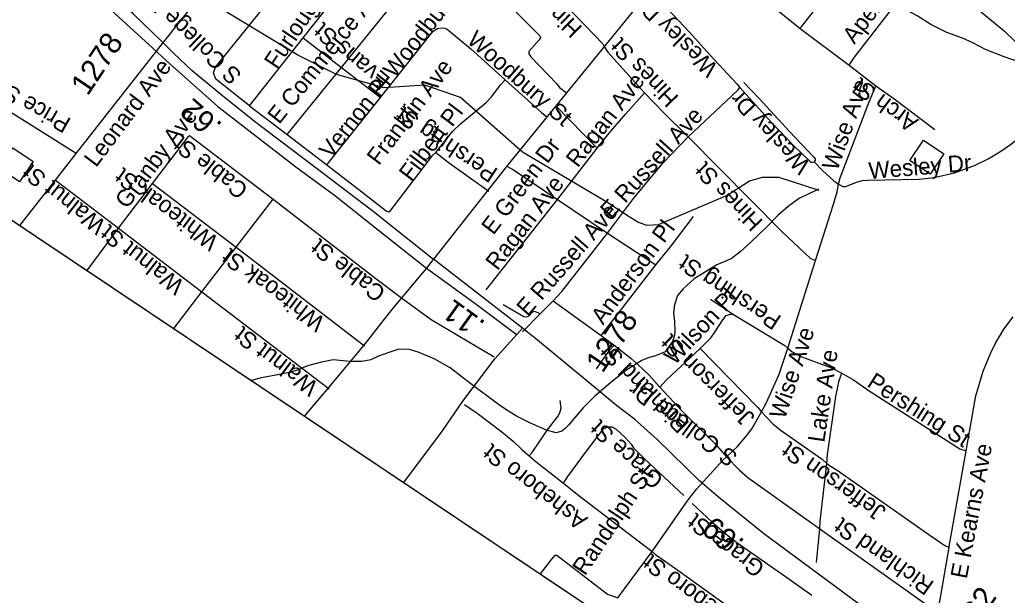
# Model space of a CAD drawing. Extents: x 1715610 to 1720914, y 798298 to 802505.
# Drawn here: x 1715709.6 to 1715831.7, y 799408.2 to 799479.3 of the extents above; entities that cross this region are included whole.
import ezdxf

# ---------------------------------------------------------------- set-up
doc = ezdxf.new("R2010")
doc.units = 0
doc.layers.add('Default', color=7, linetype='Continuous')
doc.layers.add('Prop DSN Text', color=7, linetype='Continuous')

msp = doc.modelspace()

# ---------------------------------------------------------------- linework, layer by layer
at = {"layer": 'Default'}
for p, q in [((1715610.03, 799520.5), (1715972.32, 799278.02)), ((1715610.03, 799520.5), (1715972.32, 799278.02)), ((1715727.22, 799476.39), (1715738.01, 799489.94)), ((1715749.34, 799473.4), (1715756.77, 799482.58)), ((1715806.07, 799478.23), (1715812.14, 799473.68)), ((1715737.98, 799468.67), (1715744.61, 799477.05)), ((1715744.61, 799477.05), (1715749.34, 799473.4)), ((1715726.48, 799475.44), (1715727.22, 799476.39)), ((1715765.34, 799475.71), (1715769.58, 799471.87)), ((1715716.53, 799462.76), (1715726.48, 799475.44)), ((1715742.64, 799465.11), (1715749.34, 799473.4)), ((1715749.34, 799473.4), (1715754.17, 799469.69)), ((1715812.14, 799473.68), (1715815.45, 799471.15)), ((1715747.55, 799461.35), (1715754.17, 799469.69)), ((1715716.53, 799462.76), (1715706.87, 799468.84)), ((1715737.98, 799468.67), (1715742.64, 799465.11)), ((1715775.85, 799468.67), (1715780.96, 799463.43)), ((1715742.64, 799465.11), (1715747.55, 799461.35)), ((1715713.97, 799459.49), (1715716.53, 799462.76)), ((1715776.08, 799457.08), (1715780.96, 799463.43)), ((1715747.55, 799461.35), (1715751.87, 799458.05)), ((1715709.59, 799453.87), (1715713.97, 799459.49)), ((1715713.97, 799459.49), (1715721.79, 799453.53)), ((1715721.79, 799453.53), (1715726, 799459.08)), ((1715726, 799459.08), (1715736.34, 799451.18)), ((1715736.34, 799451.18), (1715740.89, 799457.12)), ((1715767.24, 799445.91), (1715776.08, 799457.08)), ((1715776.08, 799457.08), (1715782.24, 799452.93)), ((1715717.89, 799448.31), (1715721.79, 799453.53)), ((1715721.79, 799453.53), (1715732.09, 799445.65)), ((1715782.24, 799452.93), (1715788.23, 799448.99)), ((1715732.09, 799445.65), (1715736.34, 799451.18)), ((1715736.34, 799451.18), (1715752.2, 799439)), ((1715781.46, 799440.27), (1715788.23, 799448.99)), ((1715804.57, 799438.71), (1715807.99, 799449.53)), ((1715728.63, 799441.12), (1715732.09, 799445.65)), ((1715732.09, 799445.65), (1715747.85, 799433.68)), ((1715773.92, 799442.94), (1715775.53, 799444.57)), ((1715775.53, 799444.57), (1715781.46, 799440.27)), ((1715794.99, 799444.74), (1715797.84, 799442.86)), ((1715771.76, 799440.71), (1715773.92, 799442.94)), ((1715781.46, 799440.27), (1715783.09, 799439.09)), ((1715793.32, 799421.29), (1715794.13, 799422.21)), ((1715808.12, 799412.19), (1715808.51, 799416.35)), ((1715783.53, 799407.82), (1715787.78, 799413.54))]:
    msp.add_line(p, q, dxfattribs=at)
for points in [[(1715813.67, 799533.94), (1715812.69, 799527.8), (1715812.51, 799527.2), (1715811.89, 799522.93), (1715811.77, 799521.26), (1715811.51, 799519.27), (1715811.41, 799518.19), (1715811.3, 799517.32), (1715811.12, 799515.97), (1715810.84, 799514.85), (1715810.84, 799514.53), (1715810.59, 799513.84), (1715810.47, 799513.27), (1715810.23, 799512.71), (1715808.65, 799509.73), (1715806.38, 799506.28), (1715800.8, 799499.28), (1715769.91, 799461.37), (1715760.72, 799449.69)], [(1715760.72, 799449.69), (1715760.58, 799449.8), (1715753.26, 799455.6), (1715746.04, 799461.08), (1715738.6, 799466.72), (1715734.62, 799469.89), (1715730.9, 799473.01), (1715728.54, 799475.23), (1715727.1, 799476.64), (1715723.6, 799480.04), (1715719.83, 799483.39), (1715716.72, 799486.21), (1715714.47, 799488.13), (1715712.62, 799489.82), (1715710.38, 799492.02), (1715707.79, 799494.65)], [(1715707.29, 799493.53), (1715709.98, 799490.54), (1715712.78, 799487.65), (1715719.02, 799482.24), (1715726.03, 799475.8), (1715727.72, 799474.21), (1715734.06, 799468.59), (1715743.7, 799461.13), (1715748.49, 799457.6), (1715753.92, 799453.3), (1715759.88, 799448.58)], [(1715833.21, 799474.08), (1715831.33, 799474.72), (1715829, 799475.63), (1715827.44, 799476.44), (1715826.14, 799477.01), (1715824.22, 799477.74), (1715822.25, 799478.71), (1715820.55, 799479.77), (1715818.7, 799480.77), (1715816.18, 799482.02), (1715814.93, 799482.5), (1715813.9, 799482.99), (1715812.58, 799483.69), (1715811.57, 799484.37), (1715810.48, 799485.01), (1715807.82, 799486.2), (1715805.02, 799487.59), (1715801.99, 799489.08), (1715800.78, 799489.64), (1715799.52, 799490.34), (1715797.31, 799491.64), (1715796.97, 799491.92)], [(1715737.98, 799468.67), (1715733.81, 799471.96), (1715733.52, 799472.74), (1715733.78, 799473.44), (1715747.15, 799490.05)], [(1715744.61, 799477.05), (1715751.22, 799485.41), (1715751.44, 799485.87), (1715751.45, 799486.27), (1715751.07, 799487.02), (1715747.15, 799490.05)], [(1715792.77, 799489.19), (1715798.14, 799484.7), (1715806.07, 799478.23)], [(1715808.42, 799458.19), (1715803.5, 799459.81), (1715801.38, 799459.81), (1715799.83, 799459.34), (1715797.15, 799457.6), (1715788.51, 799453.93), (1715787.15, 799453.87), (1715786.07, 799454.24), (1715784.93, 799454.92), (1715782.19, 799456.75), (1715771.75, 799462.94), (1715764.09, 799469.7), (1715759.65, 799471.21), (1715754.64, 799470.9), (1715748.73, 799472.53), (1715743.95, 799474.91), (1715735.09, 799480.3), (1715730.86, 799484.96), (1715728.22, 799486.54), (1715727.14, 799486.61)], [(1715772.83, 799485.55), (1715781.66, 799476.32), (1715781.87, 799475.93)], [(1715806.07, 799478.23), (1715808.63, 799481.48), (1715811.77, 799485.82)], [(1715787.6, 799482.88), (1715792.39, 799477.76), (1715794.92, 799474.95), (1715798.27, 799471.37), (1715798.61, 799470.91)], [(1715812.14, 799473.68), (1715812.82, 799474.67), (1715818.38, 799481.91)], [(1715769.72, 799481.48), (1715773.87, 799477.33), (1715773.96, 799477.08), (1715773.81, 799476.82), (1715772.51, 799475.37), (1715772.54, 799475.08), (1715772.79, 799474.71), (1715775.98, 799471.4), (1715776.3, 799470.93), (1715777.18, 799470.26)], [(1715827.35, 799481.2), (1715831.34, 799477.89), (1715833.79, 799475.56)], [(1715754.17, 799469.69), (1715760.69, 799477.89), (1715761.23, 799478.23), (1715761.68, 799478.32), (1715762.13, 799478.27), (1715762.41, 799478.15), (1715765.34, 799475.71)], [(1715781.87, 799475.93), (1715782.31, 799475.29), (1715786.85, 799470.25)], [(1715810.84, 799458.98), (1715811.37, 799458.68), (1715811.7, 799458.68), (1715813.16, 799459.26), (1715813.81, 799459.42), (1715814.39, 799459.48), (1715820.81, 799459.59), (1715822.65, 799459.8), (1715825.15, 799460.39), (1715827.65, 799461.28), (1715829.34, 799462.11), (1715830.77, 799462.98), (1715832.08, 799463.9), (1715834.82, 799466.01), (1715838.01, 799468.22), (1715839.01, 799469.05), (1715839.92, 799469.93), (1715841.27, 799471.57), (1715842.44, 799473.16)], [(1715761.01, 799462.9), (1715763.1, 799465.49), (1715764.06, 799466.42), (1715767.26, 799469.07), (1715767.89, 799469.77), (1715769.05, 799471.31), (1715769.58, 799471.87)], [(1715769.58, 799471.87), (1715774.09, 799467.85), (1715774.76, 799467.32)], [(1715792.22, 799464.82), (1715798.32, 799470.55), (1715798.61, 799470.91)], [(1715798.61, 799470.91), (1715802.54, 799466.6), (1715805.3, 799463.73), (1715807.31, 799461.76), (1715807.43, 799461.69), (1715807.59, 799461.69), (1715807.8, 799461.73)], [(1715799.12, 799471.55), (1715801.02, 799469.56), (1715804.77, 799465.47), (1715807.78, 799462.32), (1715807.94, 799462.12), (1715807.93, 799461.94), (1715807.8, 799461.73)], [(1715810.84, 799458.98), (1715811.01, 799459.76), (1715814.54, 799468.96), (1715815.45, 799471.15)], [(1715815.45, 799471.15), (1715817.65, 799469.57), (1715822.72, 799465.74)], [(1715780.96, 799463.43), (1715782.47, 799465.29), (1715784.47, 799467.63), (1715786.85, 799470.25)], [(1715786.85, 799470.25), (1715789.17, 799467.82), (1715792.22, 799464.82)], [(1715726, 799459.08), (1715730.45, 799464.89), (1715730.55, 799465.01), (1715740.89, 799457.12)], [(1715782.24, 799452.93), (1715785.48, 799457.19), (1715788.27, 799460.6), (1715789.15, 799461.61), (1715792.22, 799464.82)], [(1715792.22, 799464.82), (1715803.86, 799453.08), (1715807.36, 799449.79), (1715807.99, 799449.53)], [(1715751.87, 799458.05), (1715754.9, 799455.7), (1715755.17, 799455.57), (1715755.32, 799455.58), (1715760.67, 799462.57), (1715761.01, 799462.9)], [(1715761.01, 799462.9), (1715762.72, 799461.58), (1715767.57, 799458.11)], [(1715769.89, 799461.16), (1715770.64, 799460.76), (1715776.08, 799457.08)], [(1715807.8, 799461.73), (1715808.83, 799460.66), (1715810.26, 799459.38), (1715810.84, 799458.98)], [(1715807.99, 799449.53), (1715810.19, 799456.51), (1715810.65, 799458.02), (1715810.84, 799458.98)], [(1715808.34, 799458.36), (1715806.76, 799457.58), (1715806.02, 799457.24), (1715804.6, 799456.23), (1715803.31, 799455.11), (1715802, 799453.74), (1715799.99, 799451.82), (1715798.65, 799450.62), (1715797.56, 799449.74), (1715795.79, 799449), (1715792.98, 799447.28), (1715791.61, 799446.05), (1715790.93, 799445.2), (1715790.52, 799444.06), (1715790.41, 799443.13), (1715790.53, 799442), (1715790.59, 799440.85), (1715790.55, 799440.25), (1715790.31, 799439.51), (1715789.39, 799438.24), (1715788.2, 799437.74), (1715787.39, 799437.56), (1715786.49, 799437.17), (1715784.54, 799435.92), (1715782.63, 799434.43), (1715780.71, 799432.79), (1715779.23, 799431.32), (1715778, 799429.9), (1715777.47, 799429.21), (1715777.02, 799428.78), (1715776.62, 799428.42), (1715775.9, 799428.22), (1715774.71, 799428.56), (1715772.73, 799429.44), (1715771, 799430.3), (1715769.66, 799431.12), (1715768.76, 799431.73), (1715765.34, 799434.28), (1715763.91, 799435.42), (1715762.8, 799436.27), (1715760.89, 799437.32), (1715758.98, 799438.15), (1715757.77, 799438.55), (1715756.46, 799438.56), (1715755.33, 799438.22), (1715753.93, 799437.7), (1715752.98, 799437.24), (1715751.86, 799437.06), (1715750.38, 799437.07), (1715748.31, 799437.27), (1715746.89, 799436.97), (1715745.16, 799436.52), (1715743.91, 799436), (1715742.73, 799435.66), (1715741.03, 799435.34), (1715739.4, 799435.03), (1715738.22, 799434.7)], [(1715740.89, 799457.12), (1715753.42, 799447.43), (1715756.96, 799444.78)], [(1715788.23, 799448.99), (1715790.03, 799451.22), (1715792.91, 799454.97)], [(1715775.53, 799444.57), (1715776.59, 799445.71), (1715782.24, 799452.93)], [(1715760.72, 799449.69), (1715760.67, 799449.63), (1715759.88, 799448.58)], [(1715771.73, 799441.17), (1715760.72, 799449.69)], [(1715759.88, 799448.58), (1715758.97, 799447.5), (1715757.23, 799445.46), (1715755.75, 799443.69), (1715754.46, 799442.1), (1715752.27, 799439.27), (1715747.99, 799434.12), (1715744.76, 799430.32)], [(1715759.88, 799448.58), (1715765.83, 799444.28), (1715770.48, 799440.79), (1715771.05, 799440.41)], [(1715756.96, 799444.78), (1715760.44, 799442.25), (1715768.24, 799437.63)], [(1715769.33, 799444.11), (1715771.91, 799442.63), (1715772.28, 799442.57), (1715772.61, 799442.73), (1715772.89, 799443.11), (1715773.19, 799443.28), (1715773.65, 799443.1), (1715773.92, 799442.94)], [(1715793.71, 799438.64), (1715795.06, 799440.03), (1715795.53, 799440.68), (1715796.52, 799442.22), (1715796.95, 799442.74), (1715797.41, 799442.92), (1715797.84, 799442.86)], [(1715797.84, 799442.86), (1715804.19, 799439.03), (1715804.57, 799438.71)], [(1715826.62, 799426.01), (1715827.79, 799432.8), (1715828.72, 799435.86), (1715829.61, 799438.05), (1715830.22, 799439.23), (1715831.29, 799441.06), (1715832.44, 799442.58)], [(1715757.08, 799422.08), (1715761.83, 799428.5), (1715764.37, 799432.16), (1715768.31, 799437.4), (1715771.05, 799440.41)], [(1715771.05, 799440.41), (1715771.73, 799441.17)], [(1715821.88, 799401.1), (1715813.24, 799407.13), (1715801.54, 799415.8), (1715796, 799420.28), (1715793.69, 799422.27), (1715788.38, 799427.42), (1715785.59, 799429.91), (1715783.38, 799431.61), (1715779.49, 799434.84), (1715773.6, 799439.71), (1715771.73, 799441.17)], [(1715780.91, 799436.16), (1715782.58, 799438.52), (1715783.09, 799439.09)], [(1715783.09, 799439.09), (1715785.2, 799437.43), (1715786.02, 799436.7), (1715787.42, 799435.38), (1715788.73, 799433.88)], [(1715788.73, 799433.88), (1715789.54, 799434.77), (1715793.71, 799438.64)], [(1715793.71, 799438.64), (1715800.84, 799431.37), (1715801.3, 799430.83)], [(1715801.3, 799430.83), (1715801.93, 799431.99), (1715803.47, 799435.5), (1715804.57, 799438.71)], [(1715804.57, 799438.71), (1715805.1, 799438.26), (1715806.16, 799437.66), (1715809.97, 799436.28), (1715811.24, 799435.61)], [(1715809.4, 799424.46), (1715809.45, 799425.54), (1715810.51, 799432.74), (1715810.92, 799434.7), (1715811.24, 799435.61)], [(1715811.24, 799435.61), (1715812.68, 799434.78), (1715814.72, 799433.36), (1715825.85, 799426.25), (1715826.62, 799426.01)], [(1715788.73, 799433.88), (1715791.53, 799430.85), (1715795.48, 799426.94), (1715796.98, 799425.28)], [(1715764.57, 799431.73), (1715766.12, 799430.67), (1715769.18, 799428.34), (1715770.58, 799427.22), (1715771.65, 799426.19), (1715772.56, 799425.4)], [(1715772.56, 799425.4), (1715772.95, 799425.8), (1715774.82, 799428.62), (1715776.1, 799430.26), (1715776.36, 799430.71), (1715776.52, 799431.28), (1715776.38, 799432.23)], [(1715796.98, 799425.28), (1715798.33, 799426.54), (1715799.46, 799427.85), (1715800.12, 799428.73), (1715801.3, 799430.83)], [(1715801.3, 799430.83), (1715802.71, 799429.34), (1715803.59, 799428.59), (1715808.82, 799424.96), (1715809.4, 799424.46)], [(1715776.82, 799422.02), (1715777.34, 799422.84), (1715779.65, 799425.98), (1715781.77, 799428.73), (1715782.33, 799428.98), (1715782.8, 799428.99), (1715783.34, 799428.7), (1715784.45, 799427.67), (1715785.19, 799426.83), (1715785.49, 799426.38), (1715786.81, 799425), (1715791.7, 799420.49)], [(1715824.49, 799414.04), (1715824.55, 799414.41), (1715824.85, 799416.04), (1715826.62, 799426.01)], [(1715772.56, 799425.4), (1715773.43, 799424.64), (1715776.82, 799422.02)], [(1715794.13, 799422.21), (1715796.57, 799424.91), (1715796.98, 799425.28)], [(1715796.98, 799425.28), (1715798.58, 799423.63), (1715799.63, 799422.71), (1715808.51, 799416.35)], [(1715808.51, 799416.35), (1715808.55, 799417.28), (1715809.4, 799424.46)], [(1715809.4, 799424.46), (1715809.71, 799424.19), (1715810.67, 799423.61), (1715822.41, 799415.38), (1715823.97, 799414.31), (1715824.49, 799414.04)], [(1715776.82, 799422.02), (1715778.54, 799420.59), (1715787.78, 799413.54)], [(1715787.78, 799413.54), (1715792.22, 799419.95), (1715793.32, 799421.29)], [(1715792.73, 799419.5), (1715795.2, 799417.2), (1715796.97, 799415.68), (1715798.26, 799414.68), (1715804.69, 799410.2), (1715807.52, 799408.15)], [(1715808.51, 799416.35), (1715822.74, 799406.28), (1715823.09, 799406.16)], [(1715787.78, 799413.54), (1715788.21, 799413.17), (1715790.94, 799411.26), (1715803.28, 799402.38)], [(1715823.09, 799406.16), (1715823.24, 799406.66), (1715824.49, 799414.04)], [(1715773.96, 799410.78), (1715775.2, 799412.41), (1715775.8, 799413.1), (1715775.98, 799413.09), (1715782.25, 799408.28), (1715783.53, 799407.82)]]:
    msp.add_lwpolyline(points, dxfattribs=at)
for points in [[(1715707.04, 799460.93), (1715708.72, 799463.45), (1715711.23, 799461.76), (1715709.55, 799459.25)], [(1715819.64, 799461.91), (1715821.32, 799464.43), (1715823.84, 799462.74), (1715822.15, 799460.23)]]:
    msp.add_lwpolyline(points, close=True, dxfattribs=at)
at = {"layer": 'Prop DSN Text'}
msp.add_lwpolyline([(1715972.32, 799278.02), (1716250.51, 799693.66), (1715888.23, 799936.14), (1715610.03, 799520.5)], close=True, dxfattribs=at)

# ---------------------------------------------------------------- texts
at = {"layer": 'Default'}
for s, height, rotation, p in [('Furlough Ave', 2.0663, 56.2051, (1715741.36, 799473.08)), ('Woodbury St', 2.0663, 51.7198, (1715755.95, 799471.96)), ('Hines St', 2.066, 135.811, (1715779.25, 799478.36)), ('Apex Pl', 2.066, 52.445, (1715812.78, 799476.19)), ('S College Dr', 2.0663, 136.3308, (1715737.14, 799472.6)), ('E Commerce Ave', 2.0663, 51.549, (1715741.65, 799466.29)), ('Wesley Dr', 2.066, 135.4437, (1715796.06, 799473.49)), ('Evans St', 2.066, 140.093, (1715755.53, 799472.03)), ('Woodbury St', 2.0663, 318.7135, (1715764.74, 799476.57)), ('1278', 2.719, 56.2051, (1715717.96, 799469.8)), ('Hines St', 2.066, 133.9789, (1715791.17, 799469.74)), ('Leonard Ave', 2.0663, 53.0233, (1715719, 799460.96)), ('Franklin Ave', 2.0663, 52.9182, (1715753.97, 799461.2)), ('Vernon Pl', 2.066, 51.288, (1715748.03, 799461.99)), ('Ragan Ave', 2.066, 52.1122, (1715778.57, 799460.92)), ('Arch St', 2.066, 143.8373, (1715820.84, 799466.91)), ('Price St', 2.066, 150.3876, (1715716.04, 799466.99)), ('Wise Ave', 2.066, 70.1644, (1715810.67, 799460.51)), ('.62', 2.719, 138.4765, (1715734.74, 799466.41)), ('Wesley Dr', 2.066, 133.1033, (1715807.49, 799461.42)), ('Pershing St', 2.0663, 146.2051, (1715768.84, 799460.76)), ('Filbert Pl', 2.066, 52.8618, (1715757.95, 799459.21)), ('E Russell Ave', 2.0663, 47.9277, (1715782.69, 799454.58)), ('Granby Ave', 2.066, 52.7865, (1715722.83, 799455.82)), ('Cable St', 2.066, 142.2759, (1715737.96, 799458.6)), ('E Green Dr', 2.066, 52.9013, (1715768.14, 799452.59)), ('Wesley Dr', 2.066, 4.5891, (1715814.63, 799459.61)), ('Walnut St', 2.066, 141.7419, (1715720.36, 799454.22)), ('Whiteoak St', 2.0663, 143.5045, (1715734.3, 799452.26)), ('Hines St', 2.066, 133.9789, (1715801.6, 799454.4)), ('Ragan Ave', 2.066, 52.3482, (1715768.64, 799448.19)), ('E Russell Ave', 2.0663, 48.9259, (1715772.37, 799442.53)), ('Walnut St', 2.066, 142.2226, (1715730.06, 799446.78)), ('Anderson Pl', 2.0663, 53.2347, (1715781.7, 799441.48)), ('Cable St', 2.066, 142.2045, (1715754.98, 799445.87)), ('Whiteoak St', 2.0663, 143.1509, (1715747.47, 799442.24)), ('Pershing St', 2.0663, 146.8343, (1715803.9, 799442.56)), ('Wilson Pl', 2.066, 46.7374, (1715790.58, 799436.49)), ('.11', 2.719, 144.169, (1715767.28, 799441.91)), ('1278', 2.719, 56.2051, (1715781.64, 799435.5)), ('Walnut St', 2.066, 142.7096, (1715746.63, 799434.26)), ('Jefferson St', 2.0663, 135.5518, (1715800.61, 799430.28)), ('Wise Ave', 2.066, 71.4686, (1715804.18, 799429.81)), ('Richland St', 2.0663, 134.6514, (1715792.5, 799429.44)), ('Lake Ave', 2.066, 81.5617, (1715809.06, 799426.97)), ('Pershing St', 2.0663, 327.4147, (1715814.23, 799434.06)), ('S College Dr', 2.0663, 143.9601, (1715798.51, 799425.56)), ('Grace St', 2.066, 137.4026, (1715789.33, 799422.62)), ('Asheboro St', 2.0663, 142.2479, (1715779.93, 799417.69)), ('Jefferson St', 2.0663, 145.3138, (1715816.86, 799418.87)), ('E Kearns Ave', 2.0663, 79.2057, (1715826.68, 799410.1)), ('Randolph St', 2.0663, 56.2051, (1715779.48, 799410.47)), ('Grace St', 2.066, 142.9481, (1715801.87, 799411.85)), ('.69', 2.719, 140.2706, (1715799.33, 799414.86)), ('Richland St', 2.0663, 144.7689, (1715822.78, 799409.71)), ('Asheboro St', 2.0663, 143.4594, (1715799.87, 799404.33)), ('1962', 2.719, 56.2051, (1715825.99, 799401.26))]:
    msp.add_text(s, height=height, rotation=rotation, dxfattribs=at).set_placement(p)

doc.saveas('drawing.dxf')
